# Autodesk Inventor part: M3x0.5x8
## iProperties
Created: 2009-02
Part Number: M3x0.5x8
Material: 강, 연강
Description: 깊은 그루브 볼 베어링
Document SubType Name: Modeling
Standard: KS B 2023
Designer: KYOUNG IL JANG
Standards Organization: KS
Language: ko-KR
Size Designation: 6201 - 12 x 32 x 10
Categories: <MemberInstance><Categories><Category DisplayName="샤프트 부품" InternalName="7f7aeb1f-a693-4053-b835-cee3144e0d98" Mnemonic="SHFT"><Category DisplayName="베어링" Inter
Density: 7.86 g/cm^3
Mass: 36.8026 g
Surface Area: 42.5728 cm^2
Volume: 4.68226 cm^3
Vendor: CBT Solutions
Company: 한국ATC센터
IsCustomPart: 1
Author: KYOUNG IL JANG
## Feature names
1. IDS_ARRAYBALL[SIMPL:T] [Circular Pattern]
